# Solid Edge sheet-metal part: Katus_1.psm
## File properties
Author: Olev
Template: Normal.psm
Last saved by: Olev
Revision: 7
Application: Solid Edge
Accuracy: 0,990
Material Thickness: 1,00 mm
Bend Radius: 1,00 mm
Relief Width: 1,00 mm
Relief Length: 0,00 mm
Neutral Factor: 0,330
Minimum Arc Length: 0,10 mm
Deviational Tolerance: 0,10 mm
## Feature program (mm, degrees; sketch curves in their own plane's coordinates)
base tab "unnamed BaseTab 1"
flange "Flange_1"
flange "Flange_2"
jog tab "JogTab_3"  OffsetDistance = 22.7177 mm
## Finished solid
Body 1: solid body, 26 faces, 66 edges, 42 vertices.
  Faces by surface: plane 18, cylinder 8
  Edges by curve: line 50, circle 16
Bounding box of the edges (mm): 50.000 x 20.000 x 13.000, from (-25, -10, -12) to (25, 10, 1).
Cylindrical faces by radius (mm): R1 x4, R2 x4
Planar faces by outward normal: +x 4, +y 4, +z 2, -x 3, -y 2, -z 3
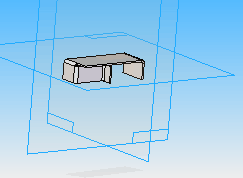
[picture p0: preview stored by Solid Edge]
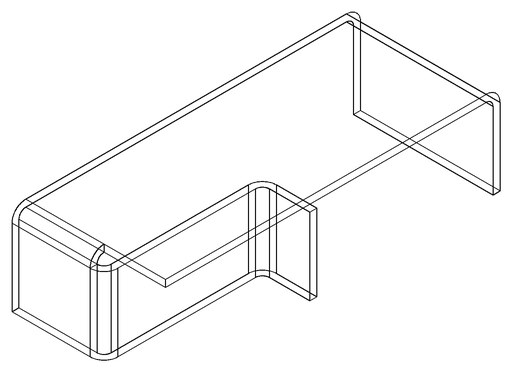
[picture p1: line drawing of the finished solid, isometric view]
